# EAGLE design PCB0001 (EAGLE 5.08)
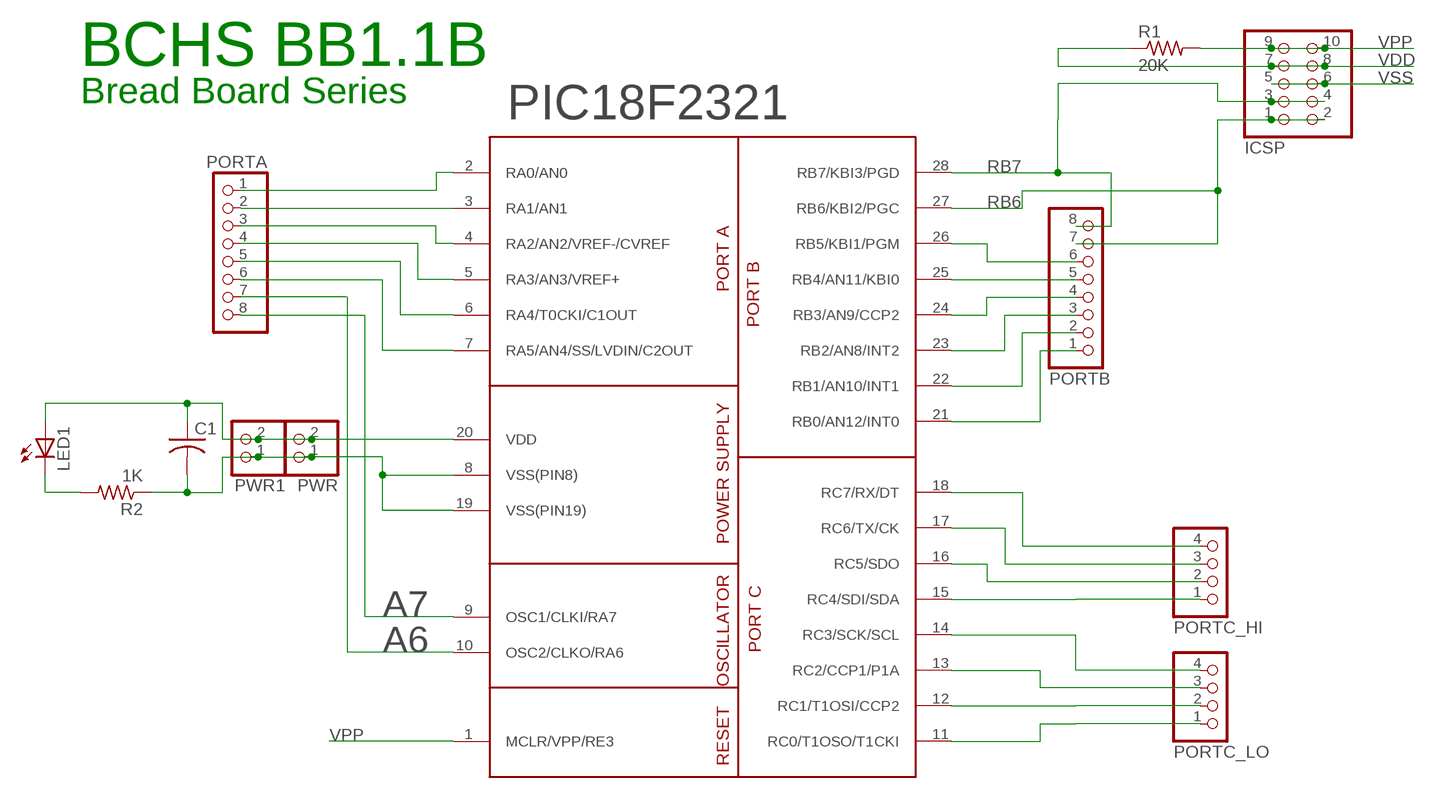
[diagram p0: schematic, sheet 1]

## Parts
C1  C-USC0805  [C0805]
ICSP  PINHD-2X5  [2X05]
LED1  LEDCHIPLED_0805  [CHIPLED_0805]
PIC18F2321  PIC18F2320SOIC  [SOIC-28]
PORTA  PINHD-1X81X08/M_  [1X08/M]
PORTB  PINHD-1X8  [1X08]
PORTC_HI  PINHD-1X4  [1X04]
PORTC_LO  PINHD-1X4  [1X04]
PWR  PINHD-1X2  [1X02]
PWR1  PINHD-1X2  [1X02]
R1  20K  R-US_R0805  [R0805]
R2  1K  R-US_R0805  [R0805]

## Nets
A6: PIC18F2321.10(OSC2/CLKO/RA6) PORTA.7
A7: PIC18F2321.9(OSC1/CLKI/RA7) PORTA.8
N$2: LED1.C R2.2
N$18: PIC18F2321.11(RC0/T1OSO/T1CKI) PORTC_LO.1
N$19: PIC18F2321.12(RC1/T1OSI/CCP2) PORTC_LO.2
N$20: PIC18F2321.13(RC2/CCP1/P1A) PORTC_LO.3
N$21: PIC18F2321.14(RC3/SCK/SCL) PORTC_LO.4
N$26: PIC18F2321.2(RA0/AN0) PORTA.1
N$27: PIC18F2321.3(RA1/AN1) PORTA.2
N$28: PIC18F2321.4(RA2/AN2/VREF-/CVREF) PORTA.3
N$29: PIC18F2321.5(RA3/AN3/VREF+) PORTA.4
N$30: PIC18F2321.6(RA4/T0CKI/C1OUT) PORTA.5
N$31: PIC18F2321.7(RA5/AN4/SS/LVDIN/C2OUT) PORTA.6
RB0: PIC18F2321.22(RB1/AN10/INT1) PORTB.2
RB1: PIC18F2321.21(RB0/AN12/INT0) PORTB.1
RB2: PIC18F2321.23(RB2/AN8/INT2) PORTB.3
RB3: PIC18F2321.24(RB3/AN9/CCP2) PORTB.4
RB4: PIC18F2321.25(RB4/AN11/KBI0) PORTB.5
RB5: PIC18F2321.26(RB5/KBI1/PGM) PORTB.6
RB6: ICSP.1 ICSP.2 PIC18F2321.27(RB6/KBI2/PGC) PORTB.7
RB7: ICSP.3 ICSP.4 PIC18F2321.28(RB7/KBI3/PGD) PORTB.8
RC4: PIC18F2321.15(RC4/SDI/SDA) PORTC_HI.1
RC5: PIC18F2321.16(RC5/SDO) PORTC_HI.2
RC6: PIC18F2321.17(RC6/TX/CK) PORTC_HI.3
RC7: PIC18F2321.18(RC7/RX/DT) PORTC_HI.4
VDD: C1.1 ICSP.7 ICSP.8 LED1.A PIC18F2321.20(VDD) PWR1.2 PWR.2 R1.1
VPP: ICSP.9 ICSP.10 PIC18F2321.1(MCLR/VPP/RE3) R1.2
VSS: C1.2 ICSP.5 ICSP.6 PIC18F2321.8(VSS(PIN8)) PIC18F2321.19(VSS(PIN19)) PWR1.1 PWR.1 R2.1

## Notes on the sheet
- BCHS BB1.1B
- Bread Board Series

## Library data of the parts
C1 = rcl:C-US: CAPACITOR, American symbol
ICSP = pinhead:PINHD-2X5: PIN HEADER
LED1 = led:LED: LED
PIC18F2321 = pic18f2320:PIC18F2320
PORTA PORTB = pinhead:PINHD-1X8: PIN HEADER
PORTC_HI PORTC_LO = pinhead:PINHD-1X4: PIN HEADER
PWR PWR1 = pinhead:PINHD-1X2: PIN HEADER
R1 R2 = rcl:R-US_: RESISTOR, American symbol

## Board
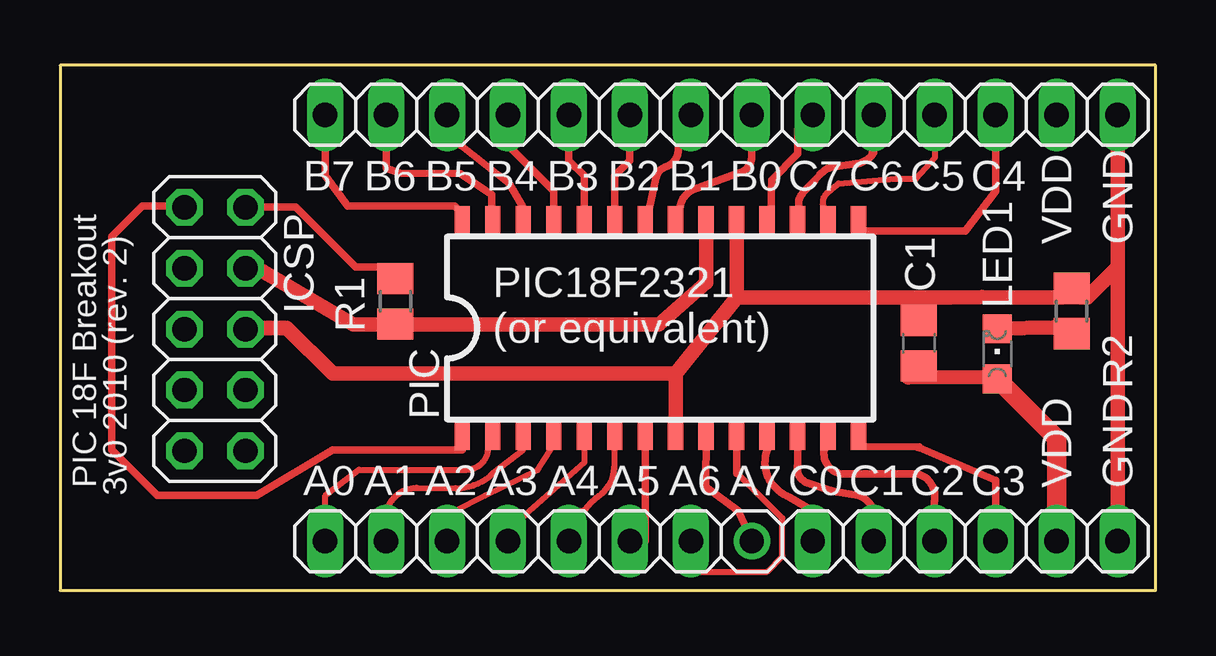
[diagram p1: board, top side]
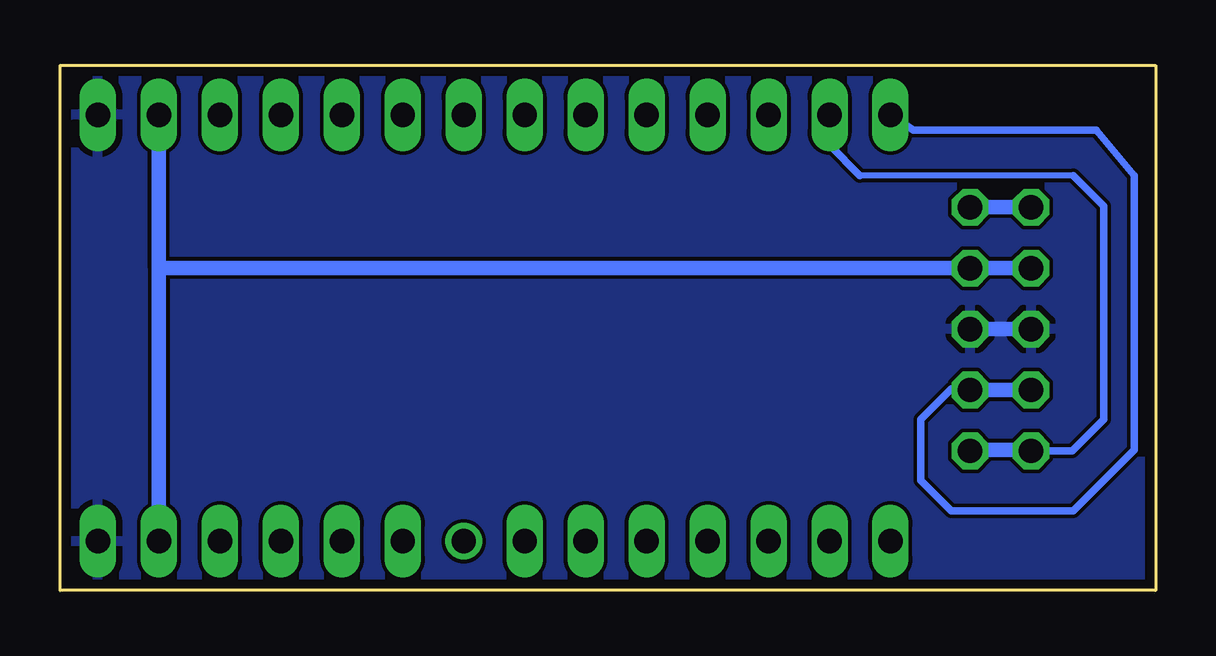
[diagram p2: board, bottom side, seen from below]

Size 45.65 x 21.89 mm. Coordinates in mm from the lower left corner, seen from the top.
Outline: 45.65,0 45.65,21.9 0,21.9 0,0 45.65,0
Copper layers (1*16): Top 0.0356mm / dielectric 1.5011mm / Bottom 0.0356mm
Design rules: minimum track width 6mil, minimum drill 13mil, track to track 6mil, track to pad 6mil, pad to pad 6mil, via to via 6mil, smd to smd 6mil, copper to edge 15mil, drill to drill 6mil, minimum pad ring 7mil, minimum via ring 7mil, stop-mask expansion 4mil, vias tented up to drill 0mil, thermal gap 10mil

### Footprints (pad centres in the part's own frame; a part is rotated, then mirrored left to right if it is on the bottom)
C0805 = smd 1.3 x 1.5: 1 -0.95,0; 2 0.95,0
2X05 = drill 1.016 octagon: 1 -5.08,-1.27; 2 -5.08,1.27; 3 -2.54,-1.27; 4 -2.54,1.27; 5 0,-1.27; 6 0,1.27; 7 2.54,-1.27; 8 2.54,1.27; 9 5.08,-1.27; 10 5.08,1.27
CHIPLED_0805 = smd 1.2 x 1.2: A 0,-1.05; C 0,1.05
SOIC-28 = smd 1.27 x 0.635: 1 -4.445,8.255; 2 -4.445,6.985; 3 -4.445,5.715; 4 -4.445,4.445; 5 -4.445,3.175; 6 -4.445,1.905; 7 -4.445,0.635; 8 -4.445,-0.635; 9 -4.445,-1.905; 10 -4.445,-3.175; 11 -4.445,-4.445; 12 -4.445,-5.715; 13 -4.445,-6.985; 14 -4.445,-8.255; 15 4.445,-8.255; 16 4.445,-6.985; 17 4.445,-5.715; 18 4.445,-4.445; 19 4.445,-3.175; 20 4.445,-1.905; 21 4.445,-0.635; 22 4.445,0.635; 23 4.445,1.905; 24 4.445,3.175; 25 4.445,4.445; 26 4.445,5.715; 27 4.445,6.985; 28 4.445,8.255
1X08/M = drill 1.016 long: 1 -8.89,0; 2 -6.35,0; 3 -3.81,0; 4 -1.27,0; 5 1.27,0; 6 3.81,0; 7 6.35,0 | drill 1.016: 8 8.89,0
1X08 = drill 1.016 long: 1 -8.89,0; 2 -6.35,0; 3 -3.81,0; 4 -1.27,0; 5 1.27,0; 6 3.81,0; 7 6.35,0; 8 8.89,0
1X04 = drill 1.016 long: 1 -3.81,0; 2 -1.27,0; 3 1.27,0; 4 3.81,0
1X02 = drill 1.016 long: 1 -1.27,0; 2 1.27,0
R0805 = smd 1.3 x 1.5: 1 -0.95,0; 2 0.95,0

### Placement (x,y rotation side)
C1  35.79,10.31 90 top
ICSP  6.46,10.9 90 top
LED1  39.06,9.87 0 top
PIC18F2321  25.02,10.95 90 top
PORTA  19.93,2.06 0 top
PORTB  19.93,19.84 180 top
PORTC_HI  35.17,19.84 180 top
PORTC_LO  35.17,2.06 0 top
PWR  42.8,2.06 180 top
PWR1  42.8,19.84 180 top
R1  13.97,12.06 90 top
R2  42.15,11.66 270 top

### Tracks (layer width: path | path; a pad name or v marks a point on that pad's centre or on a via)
A6
  Top 0.254: 28.23,4.88 30.09,3.01 30.09,1.42 29.46,0.79 26.29,0.79
  Top 0.305: PIC18F2321.10 28.19,4.88 28.23,4.88 | PORTA.7 26.29,0.79
  Bottom 0.254: PORTA.7
A7
  Top 0.254: PORTA.8 28.84,2.07
  Top 0.305: PIC18F2321.9 26.91,4.32 28.25,3.33 28.84,2.07
N$2
  Top 0.254: 38.98,10.95 40.25,10.95 LED1.C
  Top 0.406: 41.4,10.96 R2.2
  Top 0.61: LED1.C 41.4,10.96
N$18
  Top 0.305: PIC18F2321.11 29.46,5.87 arc90 30.41,3.89 31.37,3.33 PORTC_LO.1
N$19
  Top 0.305: PIC18F2321.12 30.73,5.23 arc90 31.26,4.45 32.03,4.2 32.34,4.12 33.27,3.96 arc-53 33.91,3.33 PORTC_LO.2
N$20
  Top 0.305: PIC18F2321.13 31.84,5.87 arc90 32.54,4.87 35.71,4.87 arc-90 36.42,3.69 PORTC_LO.3
N$21
  Top 0.305: PORTC_LO.4 38.98,4.6 35.82,5.94 35.75,5.96 35.8,5.99 33.14,6.01 33.16,6.9 33.27,6.78 PIC18F2321.14
N$26
  Top 0.254: PIC18F2321.2 18.04,6.52 arc43 17.84,5.97 arc-91 16.93,5.04 12.45,5.04 11.06,3.97 11.06,2.15 PORTA.1
  Top 0.305: 11.06,2.15 11.04,2.14
N$27
  Top 0.254: 13.62,3.32 arc14 13.59,3.01 | 13.62,3.32 arc-76 14.86,4.28 16.47,4.26 arc44 18.06,4.89 19.3,5.87 PIC18F2321.3 | PORTA.2 13.59,3.33 13.62,3.32
N$28
  Top 0.254: PIC18F2321.4 20.54,6.01 19.9,5.02 17.71,3.96 16.44,3.33 arc90 16.12,3.01 PORTA.3
N$29
  Top 0.254: PIC18F2321.5 21.84,6.34 21.86,5.35 19.39,3.15 18.66,2.43 PORTA.4
N$30
  Top 0.254: PIC18F2321.6 23.11,5.23 arc-53 22.47,3.96 arc16 21.84,3.33 arc90 21.2,2.69 PORTA.5
N$31
  Top 0.305: PIC18F2321.7 24.38,2.06 PORTA.6
RB0
  Top 0.305: PIC18F2321.22 24.38,15.72 24.56,15.9 24.82,17.18 arc-59 25.25,17.67 arc74 25.77,18.44 25.77,19.36 26.24,19.84 PORTB.2
RB1
  Top 0.305: PIC18F2321.21 25.83,15.94 arc-60 26.39,16.72 28.2,17.38 arc90 28.82,18.23 28.82,19.8 28.84,19.83 PORTB.1
RB2
  Top 0.305: PIC18F2321.23 23.11,17.3 23.74,17.93 PORTB.3
RB3
  Top 0.305: PIC18F2321.24 21.84,17.3 21.2,17.93 PORTB.4
RB4
  Top 0.305: PIC18F2321.25 20.57,16.66 18.66,18.57 PORTB.5
RB5
  Top 0.305: PIC18F2321.26 19.3,15.97 18.72,16.97 16.72,18.55 16.69,18.79 16.71,18.64 PORTB.6
RB6
  Top 0.305: PORTB.7 13.59,17.61 14.16,17.4 16.67,17.39 17.99,16.5 17.99,16.49 18,16.49 18,15.42 PIC18F2321.27
  Bottom 0.254: 3.42,17.3 12.32,17.3
  Bottom 0.305: ICSP.2 3.47,5.82 2.16,7.14 2.16,16.03 3.42,17.3 | 12.32,17.3 13.59,18.57 PORTB.7
  Bottom 0.61: ICSP.1 7.24,5.87 5.96,5.87 ICSP.2
RB7
  Top 0.305: PIC18F2321.28 16.76,15.71 16.44,16.03 12,16.03 11.04,17.3 PORTB.8
  Bottom 0.305: ICSP.3 8.46,8.36 8.51,8.41 9.78,7.14 9.78,4.6 8.51,3.33 3.42,3.33 0.89,5.87 0.89,17.3 2.47,19.2 10.09,19.2 PORTB.8
  Bottom 0.61: ICSP.3 ICSP.4
RC4
  Top 0.305: PORTC_HI.1 38.98,16.66 37.71,15 33.32,15 33.19,14.87 33.19,15.23 33.27,15.31 PIC18F2321.15
RC5
  Top 0.254: PIC18F2321.16 31.82,15.98 arc-65 31.99,16.6 arc-6 32.44,16.97 34.82,17.18 35.66,17.18 36.47,18.07 36.47,19.38 36.53,19.43 36.45,19.51 PORTC_HI.2
RC6
  Top 0.305: PIC18F2321.17 30.77,16.14 arc-43 31,16.63 arc7 31.66,17.33 arc-44 32.29,17.68 33.18,17.79 arc52 33.9,18.26 33.85,18.26 33.85,19.84 | 33.85,19.84 33.85,19.93 | 33.85,19.84 PORTC_HI.3
RC7
  Top 0.305: PIC18F2321.18 29.46,15.77 29.63,15.94 29.63,16.8 29.65,16.81 29.65,17.11 30.75,18.21 30.75,19.24 31.35,19.84 PORTC_HI.4
VDD
  Top 0.254: 8.46,13.3 8.51,13.49 ICSP.7 | R1.1 13.59,10.95 13.59,11.09
  Top 0.406: LED1.A 38.87,8.9 38.69,8.9 | 35.34,8.89 35.94,8.89 C1.1
  Top 0.61: PIC18F2321.20 26.92,12.85 24.95,11.09 14.22,11.09 13.59,11.09 12.95,11.09 12.21,11.09 8.46,13.3 7.74,13.48 | 38.69,8.9 35.34,8.89 38.78,8.9
  Top 0.813: PWR.2 41.52,6.35 LED1.A
  Bottom 0.61: ICSP.7 ICSP.8 41.52,13.44 | 41.52,13.44 PWR1.2 | 41.52,13.44 PWR.2
VPP
  Top 0.305: PIC18F2321.1 16.76,5.87 11.36,5.87 8.19,3.96 4.06,3.96 2.16,5.87 2.16,14.76 3.42,16.03 5.14,16.03 ICSP.10 | ICSP.9 9.82,15.98 12.32,13.49 13.5,13.49 R1.2
  Bottom 0.61: ICSP.10 ICSP.9
VSS
  Top 0.254: 35.17,12.22 35.17,10.95 C1.2
  Top 0.406: 35.73,12.22 35.7,12.18
  Top 0.61: 25.65,9.04 PIC18F2321.8 | 28.19,12.22 PIC18F2321.19 | 25.65,9.04 28.19,12.22 | 28.19,12.22 35.17,12.22 35.73,12.22 37.09,12.22 | 37.09,12.22 38.43,12.23 39.48,12.23 41.77,12.23 R2.1 42.54,12.22 42.8,12.22 44.06,13.49 | 37.09,12.22 | 44.06,13.49 PWR1.1 | 25.65,9.04 11.36,9.04 9.46,10.95 7.77,10.95 ICSP.5 | 44.06,13.49 PWR.1
  Bottom 0.61: ICSP.6 ICSP.5
  pour Bottom: 0.25,21.74 0.25,0.15 45.97,0.15 45.97,21.74

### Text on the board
tNames: B7 | B6 | B5 | B4 | B3 | B2 | B1 | B0 | C7 | C6 | C5 | C4 | VDD | GND | (or equivalent) | PIC | A0 | A1 | A2 | A3 | A4 | A5 | A6 | A7 | C0 | C1 | C2 | C3 | PIC 18F Breakout | 3v0 2010 (rev. 2) | VDD | GND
